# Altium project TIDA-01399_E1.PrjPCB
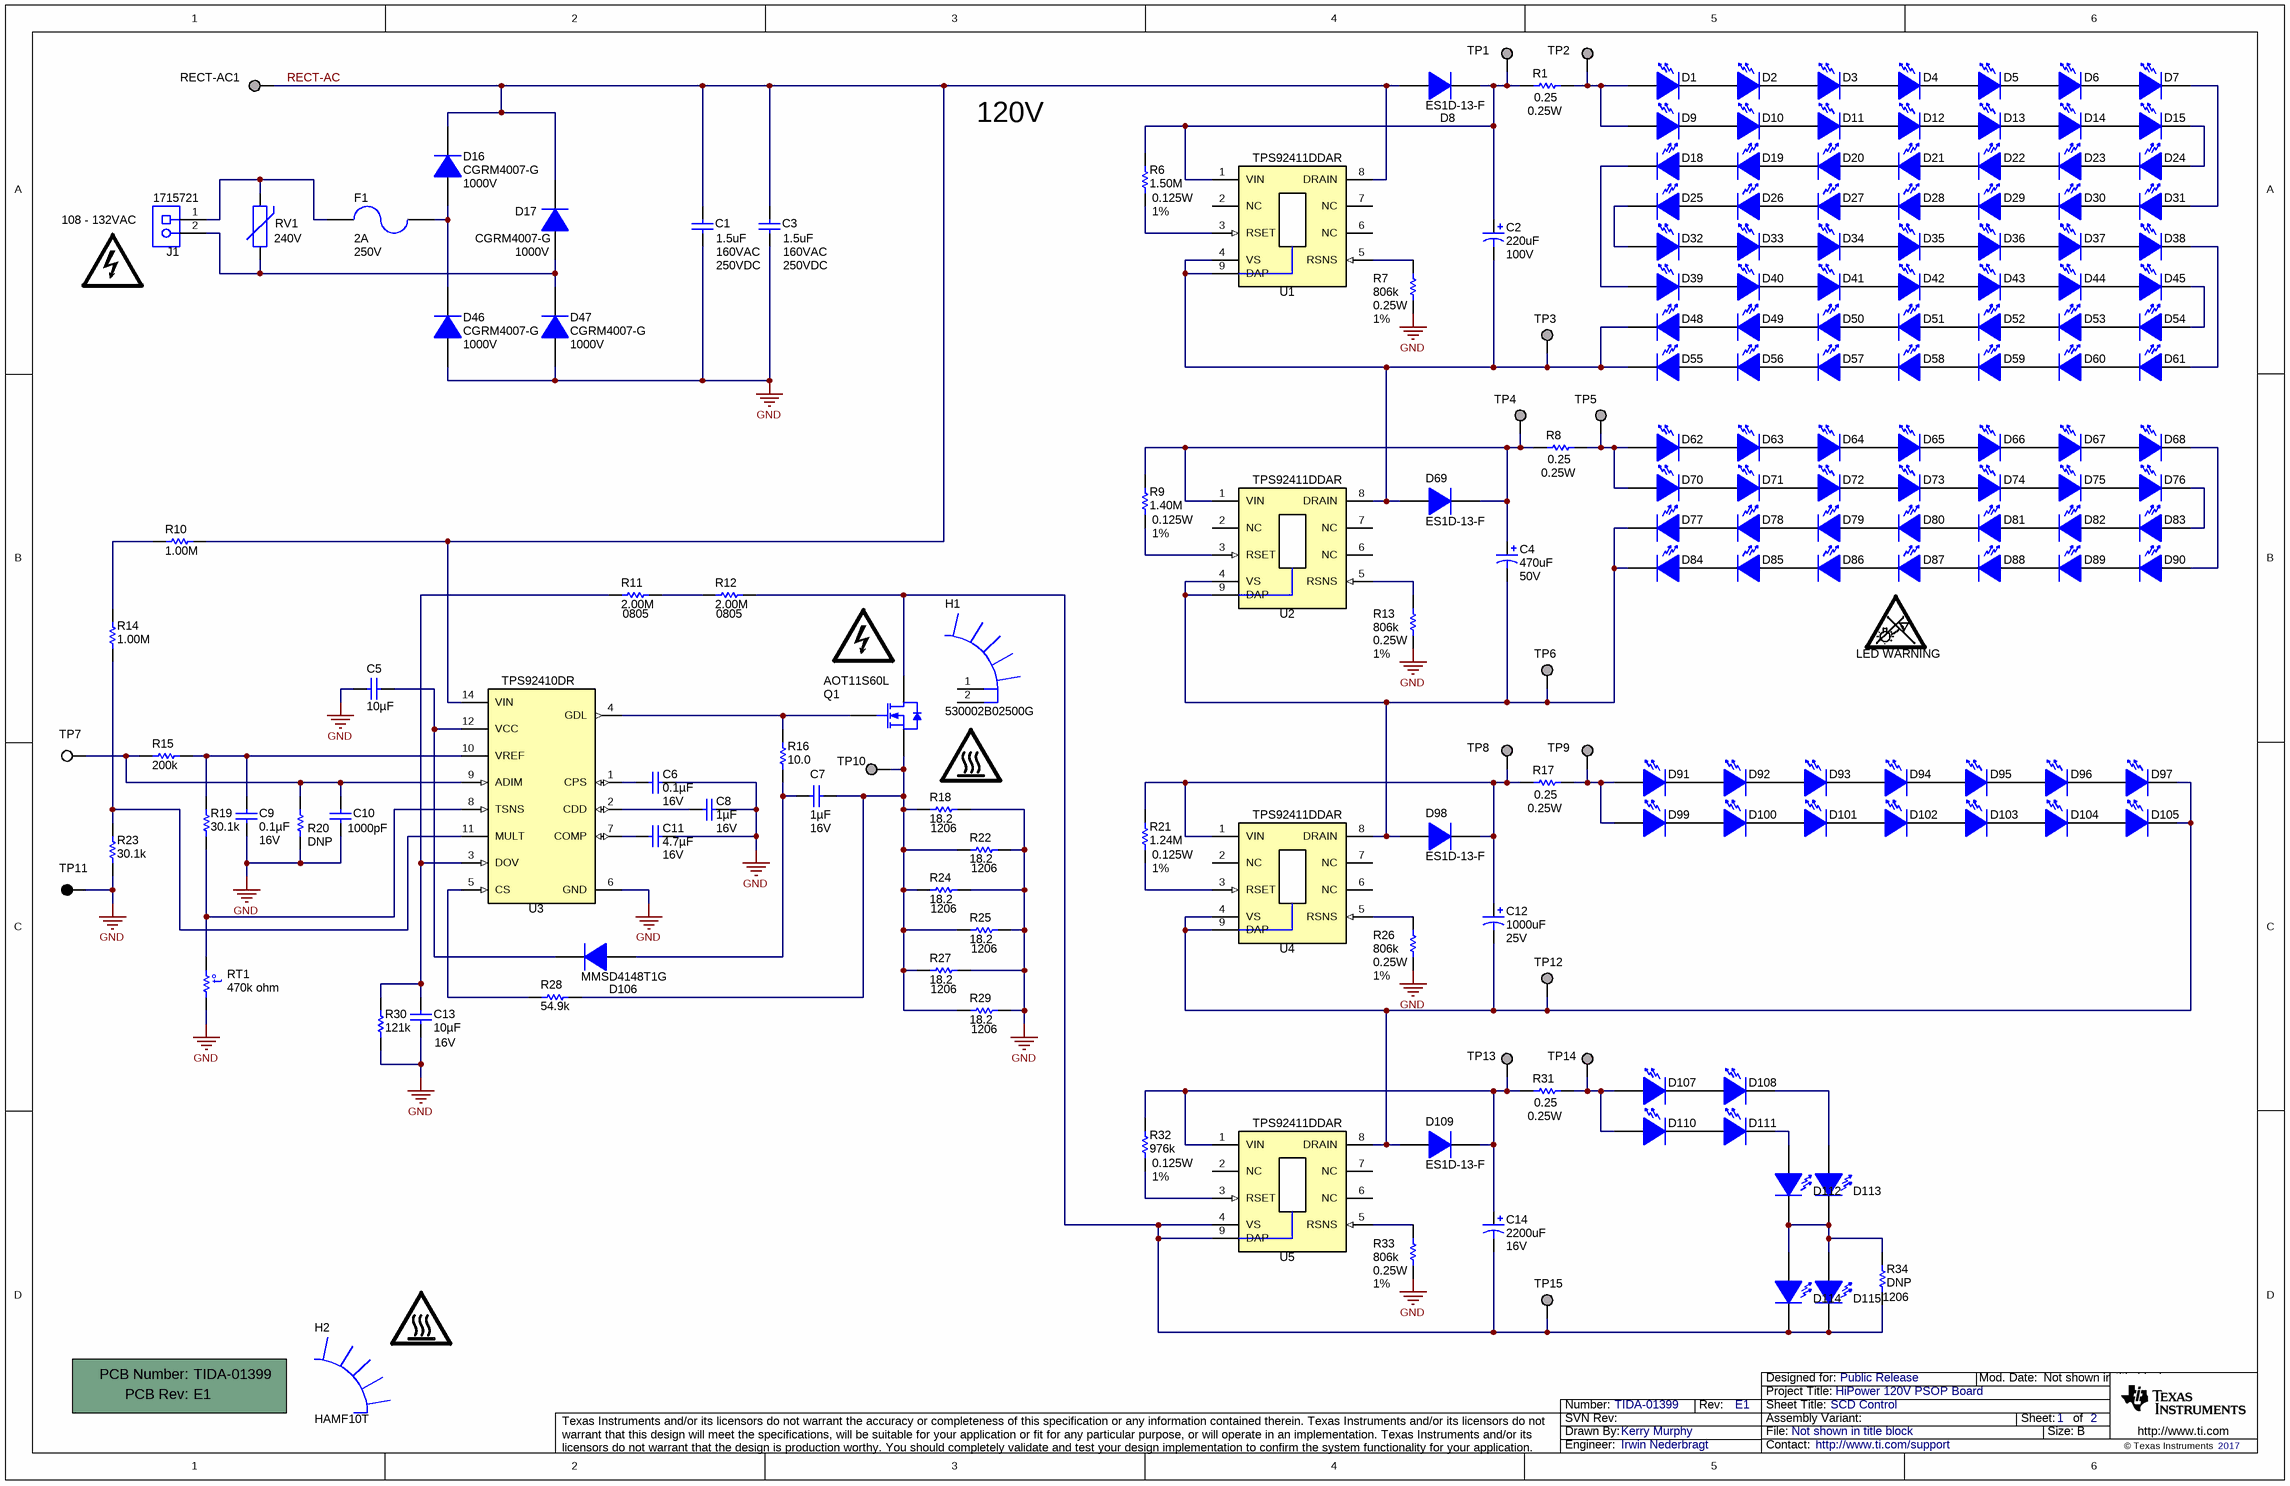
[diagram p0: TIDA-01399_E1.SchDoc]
CopyrightYear: 2017; PCB_Layout: Kerry Murphy; PCB_Rev: E1; PRJ_Customer: Public Release; PRJ_Engineer: Irwin Nederbragt; PRJ_Number: TIDA-01399; PRJ_Title: HiPower 120V PSOP Board; SCH_Rev: E1; TechSupport: http://www.ti.com/support
1 sheet, 193 parts. Net scope: global (net labels, ports and power ports of the same name join across sheets).
Board file: TIDA-01399_E1.PcbDoc

## Sheet TIDA-01399_E1.SchDoc: SCD Control
size 431 x 279 mm; Date: Not shown in title block; ApprovedBy: Not shown in title block; CheckedBy: Not shown in title block; Author: Not shown in title block; CompanyName: Not shown in title block; DrawnBy: Kerry Murphy; Engineer: Not shown in title block; Organization: Not shown in title block; Address1: Not shown in title block; Address2: Not shown in title block; Address3: Not shown in title block; Address4: Not shown in title block; DocumentNumber: 1; Revision: Use project parameter SCH_Rev; SheetNumber: 1; SheetTotal: 2; PageSetup: Record=PageOptions¦CenterHorizontal=True¦CenterVertical=True¦PrintScale=1.00¦XCorrection=1.00¦YCorrection=1.00¦PrintKind=0¦BorderSize=5000000¦LeftOffset=0¦BottomOffset=0¦Orientation=2¦PaperLength=1000¦PaperWidth=1000¦Scale=100¦PaperSource=15¦PrintQuality=600¦MediaType=1¦DitherType=10¦PaperKind=Letter¦PrintScaleMode=1

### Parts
!PCB1  Printed Circuit Board  (value not drawn)  (mechanical)
C1  value 1.5uF  VoltsAC: 160VAC  VoltsDC: 250VDC  [B32522C3155K]  (hidden comment: B32522C3155K)
C2  value 220uF  Value2Displayed: 100V  [UPW2A221MHD]  (hidden comment: UPW2A221MHD)
C3  value 1.5uF  VoltsAC: 160VAC  VoltsDC: 250VDC  [B32522C3155K]  (hidden comment: B32522C3155K)
C4  value 470uF  Value2Displayed: 50V  [UPW1H471MHD]  (hidden comment: UPW2A221MHD)
C5  ValueDisplayed: 10µF  [1206_190]  (hidden comment: C3216X7R1E106M160AE)
C6  ValueDisplayed: 0.1µF  Value2: 16V  [0603_HV]  (hidden comment: GRM188R71C104KA01D)
C7  ValueDisplayed: 1µF  Value2: 16V  [0603_HV]  (hidden comment: GRM188R71C105KA12D)
C8  ValueDisplayed: 1µF  Value2: 16V  [0603_HV]  (hidden comment: GRM188R71C105KA12D)
C9  ValueDisplayed: 0.1µF  Value2: 16V  [0603_HV]  (hidden comment: GRM188R71C104KA01D)
C10  ValueDisplayed: 1000pF  [0603_HV]  (hidden comment: GRM188R71H102KA01D)
C11  ValueDisplayed: 4.7µF  Value2: 16V  [0805_HV]  (hidden comment: GRM21BR71C475KA73L)
C12  value 1000uF  Value2Displayed: 25V  [UPW1E102MHD]  (hidden comment: UPW1E102MHD)
C13  ValueDisplayed: 10µF  Value2: 16V  [0805_HV]  (hidden comment: 0805YD106KAT2A)
C14  value 2200uF  Value2Displayed: 16V  [UPW1C222MHD]  (hidden comment: UPW1C222MHD)
D1  SPMWHT328FD5WAU0S0  [SPMWHT328FD5WAU0S0]  (value not drawn)
D2  SPMWHT328FD5WAU0S0  [SPMWHT328FD5WAU0S0]  (value not drawn)
D3  SPMWHT328FD5WAU0S0  [SPMWHT328FD5WAU0S0]  (value not drawn)
D4  SPMWHT328FD5WAU0S0  [SPMWHT328FD5WAU0S0]  (value not drawn)
D5  SPMWHT328FD5WAU0S0  [SPMWHT328FD5WAU0S0]  (value not drawn)
D6  SPMWHT328FD5WAU0S0  [SPMWHT328FD5WAU0S0]  (value not drawn)
D7  SPMWHT328FD5WAU0S0  [SPMWHT328FD5WAU0S0]  (value not drawn)
D8  ES1D-13-F  [SMA]
D9  SPMWHT328FD5WAU0S0  [SPMWHT328FD5WAU0S0]  (value not drawn)
D10  SPMWHT328FD5WAU0S0  [SPMWHT328FD5WAU0S0]  (value not drawn)
D11  SPMWHT328FD5WAU0S0  [SPMWHT328FD5WAU0S0]  (value not drawn)
D12  SPMWHT328FD5WAU0S0  [SPMWHT328FD5WAU0S0]  (value not drawn)
D13  SPMWHT328FD5WAU0S0  [SPMWHT328FD5WAU0S0]  (value not drawn)
D14  SPMWHT328FD5WAU0S0  [SPMWHT328FD5WAU0S0]  (value not drawn)
D15  SPMWHT328FD5WAU0S0  [SPMWHT328FD5WAU0S0]  (value not drawn)
D16  CGRM4007-G  value 1000V  [MINI-SMA]
D17  CGRM4007-G  value 1000V  [MINI-SMA]
D18  SPMWHT328FD5WAU0S0  [SPMWHT328FD5WAU0S0]  (value not drawn)
D19  SPMWHT328FD5WAU0S0  [SPMWHT328FD5WAU0S0]  (value not drawn)
D20  SPMWHT328FD5WAU0S0  [SPMWHT328FD5WAU0S0]  (value not drawn)
D21  SPMWHT328FD5WAU0S0  [SPMWHT328FD5WAU0S0]  (value not drawn)
D22  SPMWHT328FD5WAU0S0  [SPMWHT328FD5WAU0S0]  (value not drawn)
D23  SPMWHT328FD5WAU0S0  [SPMWHT328FD5WAU0S0]  (value not drawn)
D24  SPMWHT328FD5WAU0S0  [SPMWHT328FD5WAU0S0]  (value not drawn)
D25  SPMWHT328FD5WAU0S0  [SPMWHT328FD5WAU0S0]  (value not drawn)
D26  SPMWHT328FD5WAU0S0  [SPMWHT328FD5WAU0S0]  (value not drawn)
D27  SPMWHT328FD5WAU0S0  [SPMWHT328FD5WAU0S0]  (value not drawn)
D28  SPMWHT328FD5WAU0S0  [SPMWHT328FD5WAU0S0]  (value not drawn)
D29  SPMWHT328FD5WAU0S0  [SPMWHT328FD5WAU0S0]  (value not drawn)
D30  SPMWHT328FD5WAU0S0  [SPMWHT328FD5WAU0S0]  (value not drawn)
D31  SPMWHT328FD5WAU0S0  [SPMWHT328FD5WAU0S0]  (value not drawn)
D32  SPMWHT328FD5WAU0S0  [SPMWHT328FD5WAU0S0]  (value not drawn)
D33  SPMWHT328FD5WAU0S0  [SPMWHT328FD5WAU0S0]  (value not drawn)
D34  SPMWHT328FD5WAU0S0  [SPMWHT328FD5WAU0S0]  (value not drawn)
D35  SPMWHT328FD5WAU0S0  [SPMWHT328FD5WAU0S0]  (value not drawn)
D36  SPMWHT328FD5WAU0S0  [SPMWHT328FD5WAU0S0]  (value not drawn)
D37  SPMWHT328FD5WAU0S0  [SPMWHT328FD5WAU0S0]  (value not drawn)
D38  SPMWHT328FD5WAU0S0  [SPMWHT328FD5WAU0S0]  (value not drawn)
D39  SPMWHT328FD5WAU0S0  [SPMWHT328FD5WAU0S0]  (value not drawn)
D40  SPMWHT328FD5WAU0S0  [SPMWHT328FD5WAU0S0]  (value not drawn)
D41  SPMWHT328FD5WAU0S0  [SPMWHT328FD5WAU0S0]  (value not drawn)
D42  SPMWHT328FD5WAU0S0  [SPMWHT328FD5WAU0S0]  (value not drawn)
D43  SPMWHT328FD5WAU0S0  [SPMWHT328FD5WAU0S0]  (value not drawn)
D44  SPMWHT328FD5WAU0S0  [SPMWHT328FD5WAU0S0]  (value not drawn)
D45  SPMWHT328FD5WAU0S0  [SPMWHT328FD5WAU0S0]  (value not drawn)
D46  CGRM4007-G  value 1000V  [MINI-SMA]
D47  CGRM4007-G  value 1000V  [MINI-SMA]
D48  SPMWHT328FD5WAU0S0  [SPMWHT328FD5WAU0S0]  (value not drawn)
D49  SPMWHT328FD5WAU0S0  [SPMWHT328FD5WAU0S0]  (value not drawn)
D50  SPMWHT328FD5WAU0S0  [SPMWHT328FD5WAU0S0]  (value not drawn)
D51  SPMWHT328FD5WAU0S0  [SPMWHT328FD5WAU0S0]  (value not drawn)
D52  SPMWHT328FD5WAU0S0  [SPMWHT328FD5WAU0S0]  (value not drawn)
D53  SPMWHT328FD5WAU0S0  [SPMWHT328FD5WAU0S0]  (value not drawn)
D54  SPMWHT328FD5WAU0S0  [SPMWHT328FD5WAU0S0]  (value not drawn)
D55  SPMWHT328FD5WAU0S0  [SPMWHT328FD5WAU0S0]  (value not drawn)
D56  SPMWHT328FD5WAU0S0  [SPMWHT328FD5WAU0S0]  (value not drawn)
D57  SPMWHT328FD5WAU0S0  [SPMWHT328FD5WAU0S0]  (value not drawn)
D58  SPMWHT328FD5WAU0S0  [SPMWHT328FD5WAU0S0]  (value not drawn)
D59  SPMWHT328FD5WAU0S0  [SPMWHT328FD5WAU0S0]  (value not drawn)
D60  SPMWHT328FD5WAU0S0  [SPMWHT328FD5WAU0S0]  (value not drawn)
D61  SPMWHT328FD5WAU0S0  [SPMWHT328FD5WAU0S0]  (value not drawn)
D62  SPMWHT328FD5WAU0S0  [SPMWHT328FD5WAU0S0]  (value not drawn)
D63  SPMWHT328FD5WAU0S0  [SPMWHT328FD5WAU0S0]  (value not drawn)
D64  SPMWHT328FD5WAU0S0  [SPMWHT328FD5WAU0S0]  (value not drawn)
D65  SPMWHT328FD5WAU0S0  [SPMWHT328FD5WAU0S0]  (value not drawn)
D66  SPMWHT328FD5WAU0S0  [SPMWHT328FD5WAU0S0]  (value not drawn)
D67  SPMWHT328FD5WAU0S0  [SPMWHT328FD5WAU0S0]  (value not drawn)
D68  SPMWHT328FD5WAU0S0  [SPMWHT328FD5WAU0S0]  (value not drawn)
D69  ES1D-13-F  [SMA]
D70  SPMWHT328FD5WAU0S0  [SPMWHT328FD5WAU0S0]  (value not drawn)
D71  SPMWHT328FD5WAU0S0  [SPMWHT328FD5WAU0S0]  (value not drawn)
D72  SPMWHT328FD5WAU0S0  [SPMWHT328FD5WAU0S0]  (value not drawn)
D73  SPMWHT328FD5WAU0S0  [SPMWHT328FD5WAU0S0]  (value not drawn)
D74  SPMWHT328FD5WAU0S0  [SPMWHT328FD5WAU0S0]  (value not drawn)
D75  SPMWHT328FD5WAU0S0  [SPMWHT328FD5WAU0S0]  (value not drawn)
D76  SPMWHT328FD5WAU0S0  [SPMWHT328FD5WAU0S0]  (value not drawn)
D77  SPMWHT328FD5WAU0S0  [SPMWHT328FD5WAU0S0]  (value not drawn)
D78  SPMWHT328FD5WAU0S0  [SPMWHT328FD5WAU0S0]  (value not drawn)
D79  SPMWHT328FD5WAU0S0  [SPMWHT328FD5WAU0S0]  (value not drawn)
D80  SPMWHT328FD5WAU0S0  [SPMWHT328FD5WAU0S0]  (value not drawn)
D81  SPMWHT328FD5WAU0S0  [SPMWHT328FD5WAU0S0]  (value not drawn)
D82  SPMWHT328FD5WAU0S0  [SPMWHT328FD5WAU0S0]  (value not drawn)
D83  SPMWHT328FD5WAU0S0  [SPMWHT328FD5WAU0S0]  (value not drawn)
D84  SPMWHT328FD5WAU0S0  [SPMWHT328FD5WAU0S0]  (value not drawn)
D85  SPMWHT328FD5WAU0S0  [SPMWHT328FD5WAU0S0]  (value not drawn)
D86  SPMWHT328FD5WAU0S0  [SPMWHT328FD5WAU0S0]  (value not drawn)
D87  SPMWHT328FD5WAU0S0  [SPMWHT328FD5WAU0S0]  (value not drawn)
D88  SPMWHT328FD5WAU0S0  [SPMWHT328FD5WAU0S0]  (value not drawn)
D89  SPMWHT328FD5WAU0S0  [SPMWHT328FD5WAU0S0]  (value not drawn)
D90  SPMWHT328FD5WAU0S0  [SPMWHT328FD5WAU0S0]  (value not drawn)
D91  SPMWHT328FD5WAU0S0  [SPMWHT328FD5WAU0S0]  (value not drawn)
D92  SPMWHT328FD5WAU0S0  [SPMWHT328FD5WAU0S0]  (value not drawn)
D93  SPMWHT328FD5WAU0S0  [SPMWHT328FD5WAU0S0]  (value not drawn)
D94  SPMWHT328FD5WAU0S0  [SPMWHT328FD5WAU0S0]  (value not drawn)
D95  SPMWHT328FD5WAU0S0  [SPMWHT328FD5WAU0S0]  (value not drawn)
D96  SPMWHT328FD5WAU0S0  [SPMWHT328FD5WAU0S0]  (value not drawn)
D97  SPMWHT328FD5WAU0S0  [SPMWHT328FD5WAU0S0]  (value not drawn)
D98  ES1D-13-F  [SMA]
D99  SPMWHT328FD5WAU0S0  [SPMWHT328FD5WAU0S0]  (value not drawn)
D100  SPMWHT328FD5WAU0S0  [SPMWHT328FD5WAU0S0]  (value not drawn)
D101  SPMWHT328FD5WAU0S0  [SPMWHT328FD5WAU0S0]  (value not drawn)
D102  SPMWHT328FD5WAU0S0  [SPMWHT328FD5WAU0S0]  (value not drawn)
D103  SPMWHT328FD5WAU0S0  [SPMWHT328FD5WAU0S0]  (value not drawn)
D104  SPMWHT328FD5WAU0S0  [SPMWHT328FD5WAU0S0]  (value not drawn)
D105  SPMWHT328FD5WAU0S0  [SPMWHT328FD5WAU0S0]  (value not drawn)
D106  MMSD4148T1G  [SOD-123]
D107  SPMWHT328FD5WAU0S0  [SPMWHT328FD5WAU0S0]  (value not drawn)
D108  SPMWHT328FD5WAU0S0  [SPMWHT328FD5WAU0S0]  (value not drawn)
D109  ES1D-13-F  [SMA]
D110  SPMWHT328FD5WAU0S0  [SPMWHT328FD5WAU0S0]  (value not drawn)
D111  SPMWHT328FD5WAU0S0  [SPMWHT328FD5WAU0S0]  (value not drawn)
D112  SPMWHT328FD5WAU0S0  [SPMWHT328FD5WAU0S0]  (value not drawn)
D113  SPMWHT328FD5WAU0S0  [SPMWHT328FD5WAU0S0]  (value not drawn)
D114  SPMWHT328FD5WAU0S0  [SPMWHT328FD5WAU0S0]  (value not drawn)
D115  SPMWHT328FD5WAU0S0  [SPMWHT328FD5WAU0S0]  (value not drawn)
F1  VAC_V: 250V  Irating_A: 2A  [FUSE_RST]  (hidden comment: RST 2)
H1  530002B02500G  [Aavid_530002B02500G]
H2  HAMF10T  [Htsk_HAMF10T]
J1  1715721  [PhoenixContact_1715721]
LOGO2  DANGER HIGH VOLTAGE  [IEC_HighVoltage_Small]  (value not drawn)  (no BOM)
LOGO3  DANGER HIGH VOLTAGE  [IEC_HighVoltage_Small]  (value not drawn)  (no BOM)
LOGO4  CAUTION HOT SURFACE  [IEC_HotSurface_Small]  (value not drawn)  (no BOM)
LOGO5  CAUTION HOT SURFACE  [IEC_HotSurface_Small]  (value not drawn)  (no BOM)
LOGO6  LED WARNING  [LED_Warning]  (no BOM)
Q1  AOT11S60L  [TO-220AB]
R1  Power_W: 0.25W  ValueDisplayed: 0.25  [0805_HV]  (hidden comment: CSR0805FKR250)
R6  ValueDisplayed: 1.50M  Value1: 1%  Value2: 0.125W  [0805_HV]  (hidden comment: CRCW08051M50FKEA)
R7  ValueDisplayed: 806k  Value1: 1%  Value2: 0.25W  [1206]  (hidden comment: CRCW1206806KFKEA)
R8  Power_W: 0.25W  ValueDisplayed: 0.25  [0805_HV]  (hidden comment: CSR0805FKR250)
R9  ValueDisplayed: 1.40M  Value1: 1%  Value2: 0.125W  [0805_HV]  (hidden comment: CRCW08051M40FKEA)
R10  ValueDisplayed: 1.00M  [1206]  (hidden comment: CRCW12061M00FKEA)
R11  ValueDisplayed: 2.00M  PackageReference: 0805  [0805_HV]  (hidden comment: CRCW08052M00FKEA)
R12  ValueDisplayed: 2.00M  PackageReference: 0805  [0805_HV]  (hidden comment: CRCW08052M00FKEA)
R13  ValueDisplayed: 806k  Value1: 1%  Value2: 0.25W  [1206]  (hidden comment: CRCW1206806KFKEA)
R14  ValueDisplayed: 1.00M  [1206]  (hidden comment: CRCW12061M00FKEA)
R15  ValueDisplayed: 200k  [0603_HV]  (hidden comment: CRCW0603200KFKEA)
R16  ValueDisplayed: 10.0  [0603_HV]  (hidden comment: CRCW060310R0FKEA)
R17  Power_W: 0.25W  ValueDisplayed: 0.25  [0805_HV]  (hidden comment: CSR0805FKR250)
R18  ValueDisplayed: 18.2  [1206]  (hidden comment: CRCW120618R2FKEA)
R19  ValueDisplayed: 30.1k  [0603_HV]  (hidden comment: CRCW060330K1FKEA)
R20  DNP  [0603_HV]
R21  ValueDisplayed: 1.24M  Value1: 1%  Value2: 0.125W  [0805_HV]  (hidden comment: CRCW08051M24FKEA)
R22  ValueDisplayed: 18.2  [1206]  (hidden comment: CRCW120618R2FKEA)
R23  ValueDisplayed: 30.1k  [0603_HV]  (hidden comment: CRCW060330K1FKEA)
R24  ValueDisplayed: 18.2  [1206]  (hidden comment: CRCW120618R2FKEA)
R25  ValueDisplayed: 18.2  [1206]  (hidden comment: CRCW120618R2FKEA)
R26  ValueDisplayed: 806k  Value1: 1%  Value2: 0.25W  [1206]  (hidden comment: CRCW1206806KFKEA)
R27  ValueDisplayed: 18.2  [1206]  (hidden comment: CRCW120618R2FKEA)
R28  ValueDisplayed: 54.9k  [0603_HV]  (hidden comment: CRCW060354K9FKEA)
R29  ValueDisplayed: 18.2  [1206]  (hidden comment: CRCW120618R2FKEA)
R30  ValueDisplayed: 121k  [0603_HV]  (hidden comment: CRCW0603121KFKEA)
R31  Power_W: 0.25W  ValueDisplayed: 0.25  [0805_HV]  (hidden comment: CSR0805FKR250)
R32  ValueDisplayed: 976k  Value1: 1%  Value2: 0.125W  [0805_HV]  (hidden comment: CRCW0805976KFKEA)
R33  ValueDisplayed: 806k  Value1: 1%  Value2: 0.25W  [1206]  (hidden comment: CRCW1206806KFKEA)
R34  DNP  [1206]
RECT-AC1  Suggest using a net name here  [Keystone1502-2]  (value not drawn)
RT1  value 470k ohm  [0603_HV]  (hidden comment: NCP18WM474E03RB)
RV1  Varistor Voltage (Typ): 240V  [MOV-10D241K]  (hidden comment: MOV-10D241K)
TP1  Suggest using a net name here  [Keystone1502-2]  (value not drawn)
TP2  Suggest using a net name here  [Keystone1502-2]  (value not drawn)
TP3  Suggest using a net name here  [Keystone1502-2]  (value not drawn)
TP4  Suggest using a net name here  [Keystone1502-2]  (value not drawn)
TP5  Suggest using a net name here  [Keystone1502-2]  (value not drawn)
TP6  Suggest using a net name here  [Keystone1502-2]  (value not drawn)
TP7  5002  [Keystone5002]  (value not drawn)
TP8  Suggest using a net name here  [Keystone1502-2]  (value not drawn)
TP9  Suggest using a net name here  [Keystone1502-2]  (value not drawn)
TP10  Suggest using a net name here  [Keystone1502-2]  (value not drawn)
TP11  5001  [Keystone5001]  (value not drawn)
TP12  Suggest using a net name here  [Keystone1502-2]  (value not drawn)
TP13  Suggest using a net name here  [Keystone1502-2]  (value not drawn)
TP14  Suggest using a net name here  [Keystone1502-2]  (value not drawn)
TP15  Suggest using a net name here  [Keystone1502-2]  (value not drawn)
U1  TPS92411DDAR  [DDA0008E_N]
U2  TPS92411DDAR  [DDA0008E_N]
U3  TPS92410DR  [D0013A_N]
U4  TPS92411DDAR  [DDA0008E_N]
U5  TPS92411DDAR  [DDA0008E_N]

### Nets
GND: C1.2 C3.2 C5.2 C6.1 C8.1 C9.2 C10.2 C11.1 C13.2 D46.2(A) D47.2(A) R7.1 R13.1 R18.2 R20.1 R22.2 R23.1 R24.2 R25.2 R26.1 R27.2 R29.2 R30.1 R33.1 RT1.1 TP11.1 U3.6(GND)
RECT-AC: C1.1 C3.1 D8.2(A) D16.1(K) D17.1(K) R10.1 RECT-AC1.1 U1.8(DRAIN) U3.14(VIN)
NetC2_1: C2.1(+) D8.1(K) R1.1 R6.2 TP1.1 U1.1(VIN)
NetC2_2: C2.2(-) D48.2(K) D55.2(K) D69.2(A) TP3.1 U1.4(VS) U1.9(DAP) U2.8(DRAIN)
NetC4_1: C4.1(+) D69.1(K) R8.1 R9.2 TP4.1 U2.1(VIN)
NetC4_2: C4.2(-) D77.2(K) D84.2(K) D98.2(A) TP6.1 U2.4(VS) U2.9(DAP) U4.8(DRAIN)
NetC5_1: C5.1 D106.1(K) U3.12(VCC)
NetC6_2: C6.2 U3.1(CPS)
NetC7_1: C7.1 Q1.3(S) R18.1 R22.1 R24.1 R25.1 R27.1 R28.2 R29.1 TP10.1
NetC7_2: C7.2 D106.2(A) R16.1
NetC8_2: C8.2 U3.2(CDD)
NetC9_1: C9.1 R15.2 R19.2 U3.10(VREF)
NetC10_1: C10.1 R15.1 R20.2 TP7.1 U3.9(ADIM)
NetC11_2: C11.2 U3.7(COMP)
NetC12_1: C12.1(+) D98.1(K) R17.1 R21.2 TP8.1 U4.1(VIN)
NetC12_2: C12.2(-) D97.2(K) D105.2(K) D109.2(A) TP12.1 U4.4(VS) U4.9(DAP) U5.8(DRAIN)
NetC13_1: C13.1 R11.1 R30.2 U3.3(DOV)
NetC14_1: C14.1(+) D109.1(K) R31.1 R32.2 TP13.1 U5.1(VIN)
NetC14_2: C14.2(-) D114.2(K) D115.2(K) Q1.2(D) R12.2 R34.1 TP15.1 U5.4(VS) U5.9(DAP)
NetD1_1: D1.1(A) D9.1(A) R1.2 TP2.1
NetD1_2: D1.2(K) D2.1(A)
NetD2_2: D2.2(K) D3.1(A)
NetD3_2: D3.2(K) D4.1(A)
NetD4_2: D4.2(K) D5.1(A)
NetD5_2: D5.2(K) D6.1(A)
NetD6_2: D6.2(K) D7.1(A)
NetD7_2: D7.2(K) D31.1(A)
NetD9_2: D9.2(K) D10.1(A)
NetD10_2: D10.2(K) D11.1(A)
NetD11_2: D11.2(K) D12.1(A)
NetD12_2: D12.2(K) D13.1(A)
NetD13_2: D13.2(K) D14.1(A)
NetD14_2: D14.2(K) D15.1(A)
NetD15_2: D15.2(K) D24.1(A)
NetD16_2: D16.2(A) D46.1(K) F1.1
NetD17_2: D17.2(A) D47.1(K) J1.2 RV1.1
NetD18_1: D18.1(A) D19.2(K)
NetD18_2: D18.2(K) D39.1(A)
NetD19_1: D19.1(A) D20.2(K)
NetD20_1: D20.1(A) D21.2(K)
NetD21_1: D21.1(A) D22.2(K)
NetD22_1: D22.1(A) D23.2(K)
NetD23_1: D23.1(A) D24.2(K)
NetD25_1: D25.1(A) D26.2(K)
NetD25_2: D25.2(K) D32.1(A)
NetD26_1: D26.1(A) D27.2(K)
NetD27_1: D27.1(A) D28.2(K)
NetD28_1: D28.1(A) D29.2(K)
NetD29_1: D29.1(A) D30.2(K)
NetD30_1: D30.1(A) D31.2(K)
NetD32_2: D32.2(K) D33.1(A)
NetD33_2: D33.2(K) D34.1(A)
NetD34_2: D34.2(K) D35.1(A)
NetD35_2: D35.2(K) D36.1(A)
NetD36_2: D36.2(K) D37.1(A)
NetD37_2: D37.2(K) D38.1(A)
NetD38_2: D38.2(K) D61.1(A)
NetD39_2: D39.2(K) D40.1(A)
NetD40_2: D40.2(K) D41.1(A)
NetD41_2: D41.2(K) D42.1(A)
NetD42_2: D42.2(K) D43.1(A)
NetD43_2: D43.2(K) D44.1(A)
NetD44_2: D44.2(K) D45.1(A)
NetD45_2: D45.2(K) D54.1(A)
NetD48_1: D48.1(A) D49.2(K)
NetD49_1: D49.1(A) D50.2(K)
NetD50_1: D50.1(A) D51.2(K)
NetD51_1: D51.1(A) D52.2(K)
NetD52_1: D52.1(A) D53.2(K)
NetD53_1: D53.1(A) D54.2(K)
NetD55_1: D55.1(A) D56.2(K)
NetD56_1: D56.1(A) D57.2(K)
NetD57_1: D57.1(A) D58.2(K)
NetD58_1: D58.1(A) D59.2(K)
NetD59_1: D59.1(A) D60.2(K)
NetD60_1: D60.1(A) D61.2(K)
NetD62_1: D62.1(A) D70.1(A) R8.2 TP5.1
NetD62_2: D62.2(K) D63.1(A)
NetD63_2: D63.2(K) D64.1(A)
NetD64_2: D64.2(K) D65.1(A)
NetD65_2: D65.2(K) D66.1(A)
NetD66_2: D66.2(K) D67.1(A)
NetD67_2: D67.2(K) D68.1(A)
NetD68_2: D68.2(K) D90.1(A)
NetD70_2: D70.2(K) D71.1(A)
NetD71_2: D71.2(K) D72.1(A)
NetD72_2: D72.2(K) D73.1(A)
NetD73_2: D73.2(K) D74.1(A)
NetD74_2: D74.2(K) D75.1(A)
NetD75_2: D75.2(K) D76.1(A)
NetD76_2: D76.2(K) D83.1(A)
NetD77_1: D77.1(A) D78.2(K)
NetD78_1: D78.1(A) D79.2(K)
NetD79_1: D79.1(A) D80.2(K)
NetD80_1: D80.1(A) D81.2(K)
NetD81_1: D81.1(A) D82.2(K)
NetD82_1: D82.1(A) D83.2(K)
NetD84_1: D84.1(A) D85.2(K)
NetD85_1: D85.1(A) D86.2(K)
NetD86_1: D86.1(A) D87.2(K)
NetD87_1: D87.1(A) D88.2(K)
NetD88_1: D88.1(A) D89.2(K)
NetD89_1: D89.1(A) D90.2(K)
NetD91_1: D91.1(A) D99.1(A) R17.2 TP9.1
NetD91_2: D91.2(K) D92.1(A)
NetD92_2: D92.2(K) D93.1(A)
NetD93_2: D93.2(K) D94.1(A)
NetD94_2: D94.2(K) D95.1(A)
NetD95_2: D95.2(K) D96.1(A)
NetD96_2: D96.2(K) D97.1(A)
NetD99_2: D99.2(K) D100.1(A)
NetD100_2: D100.2(K) D101.1(A)
NetD101_2: D101.2(K) D102.1(A)
NetD102_2: D102.2(K) D103.1(A)
NetD103_2: D103.2(K) D104.1(A)
NetD104_2: D104.2(K) D105.1(A)
NetD107_1: D107.1(A) D110.1(A) R31.2 TP14.1
NetD107_2: D107.2(K) D108.1(A)
NetD108_2: D108.2(K) D113.1(A)
NetD110_2: D110.2(K) D111.1(A)
NetD111_2: D111.2(K) D112.1(A)
NetD112_2: D112.2(K) D113.2(K) D114.1(A) D115.1(A) R34.2
NetF1_2: F1.2 J1.1 RV1.2
NetQ1_1: Q1.1(G) R16.2 U3.4(GDL)
NetR6_1: R6.1 U1.3(RSET)
NetR7_2: R7.2 U1.5(RSNS)
NetR9_1: R9.1 U2.3(RSET)
NetR10_2: R10.2 R14.2
NetR11_2: R11.2 R12.1
NetR13_2: R13.2 U2.5(RSNS)
NetR14_1: R14.1 R23.2 U3.11(MULT)
NetR19_1: R19.1 RT1.2 U3.8(TSNS)
NetR21_1: R21.1 U4.3(RSET)
NetR26_2: R26.2 U4.5(RSNS)
NetR28_1: R28.1 U3.5(CS)
NetR32_1: R32.1 U5.3(RSET)
NetR33_2: R33.2 U5.5(RSNS)

Not connected (* = marked no-connect by the designer): H1 1 2; U1 2(NC) 6(NC) 7(NC); U2 2(NC) 6(NC) 7(NC); U4 2(NC) 6(NC) 7(NC); U5 2(NC) 6(NC) 7(NC)

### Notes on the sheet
- 120V
- 108 - 132VAC

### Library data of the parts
!PCB1 = PCB: Manufacturer: Any; PartNumber: TIDA-01399; SymbolCreator: a0412235
C1 C3 = Capacitor: CAP, Film, 1.5uF, 160VAC, 250VDC, 10%, Radial; Manufacturer: EPCOS; Polarized: N; U/M: EA; lead_free_status: Lead Free; lead_length: 0.006; dielectric_material: Polyester; voltage_rating_dc: 250.0; size_height: 0.0175; size_length: 0.018
C2 = UPW2A221MHD: CAP, AL, 220µF, 100V, +/- 20%, Radial; Manufacturer: Nichicon; Tolerance_%: 20; VDC_V: 100
C4 = UPW2A221MHD: CAP, AL, 470µF, 50V, +/- 20%, Radial; Manufacturer: Nichicon; Tolerance_%: 20; VDC_V: 50
C5 = C3216X7R1E106M160AE: CAP, CERM, 10 µF, 25 V, +/- 20%, X7R, 1206_190; Manufacturer: TDK; Polarized: N; CompType: Capacitor; Value: 10uF; U/M: EA; Cap_F: 0.00001; Tolerance_%: 20; Value1: Unknown; VDC_V: 25; Value2: 25V; TaMin_C: -55; TaMax_C: 125; Cap_Case: 1206; SizeArea_mm2: 5.12; SizeAreaWB_mm2: 10.92; SizeX_mm: 3.2; SizeY_mm: 1.6; SizeZ_mm: 1.9; AEC Category: Q200
C6 C9 = GRM188R71C104KA01D: CAP, CERM, 0.1 µF, 16 V, +/- 10%, X7R, 0603; Manufacturer: MuRata; Polarized: N; CompType: Capacitor; Value: 0.1uF; U/M: EA; Cap_F: 0.0000001; Tolerance_%: 10; Value1: Unknown; VDC_V: 16; TaMin_C: -55; TaMax_C: 125; Cap_Case: 0603; SizeArea_mm2: 1.28; SizeAreaWB_mm2: 4.68; SizeX_mm: 1.6; SizeY_mm: 0.8; SizeZ_mm: 1; AEC Category: Q200
C7 C8 = GRM188R71C105KA12D: CAP, CERM, 1 µF, 16 V, +/- 10%, X7R, 0603; Manufacturer: MuRata; Polarized: N; CompType: Capacitor; Value: 1uF; U/M: EA; Cap_F: 0.000001; Tolerance_%: 10; ESR_ohm: 0.011; Value1: 0.011 ohm; VDC_V: 16; TaMin_C: -55; TaMax_C: 125; Cap_Case: 0603; SizeArea_mm2: 1.28; SizeAreaWB_mm2: 4.68; SizeX_mm: 1.6; SizeY_mm: 0.8; SizeZ_mm: 1; AEC Category: Q200
C10 = GRM188R71H102KA01D: CAP, CERM, 1000 pF, 50 V, +/- 10%, X7R, 0603; Manufacturer: MuRata; Polarized: N; CompType: Capacitor; Value: 1000pF; U/M: EA; Cap_F: 0.000000001; Tolerance_%: 10; Value1: Unknown; VDC_V: 50; Value2: 50V; TaMin_C: -55; TaMax_C: 125; Cap_Case: 0603; SizeArea_mm2: 1.28; SizeAreaWB_mm2: 4.68; SizeX_mm: 1.6; SizeY_mm: 0.8; SizeZ_mm: 1; AEC Category: Q200
C11 = GRM21BR71C475KA73L: CAP, CERM, 4.7 µF, 16 V, +/- 10%, X7R, 0805; Manufacturer: MuRata; Polarized: N; CompType: Capacitor; Value: 4.7uF; U/M: EA; Cap_F: 0.0000047; Tolerance_%: 10; ESR_ohm: 0.006; Value1: 0.006 ohm; VDC_V: 16; TaMin_C: -55; TaMax_C: 125; Cap_Case: 0805; SizeArea_mm2: 2.5; SizeAreaWB_mm2: 6.75; SizeX_mm: 2; SizeY_mm: 1.25; SizeZ_mm: 1.45; AEC Category: Q200
C12 = UPW1E102MHD: CAP, AL, 1000µF, 25V, +/- 20%, Radial; Manufacturer: Nichicon; U/M: EA; Tolerance_%: 20; VDC_V: 25
C13 = 0805YD106KAT2A: CAP, CERM, 10 µF, 16 V, +/- 10%, X5R, 0805; Manufacturer: AVX; Polarized: N; CompType: Capacitor; Value: 10uF; U/M: EA; Cap_F: 0.00001; Tolerance_%: 10; Value1: Unknown; VDC_V: 16; TaMin_C: -55; TaMax_C: 85; Cap_Case: 0805; SizeArea_mm2: 2.5; SizeAreaWB_mm2: 6.75; SizeX_mm: 2; SizeY_mm: 1.25; SizeZ_mm: 1.45; AEC Category: Q200
C14 = UPW1C222MHD: CAP, AL, 2200µF, 16V, +/- 20%, Radial; Manufacturer: Nichicon; Tolerance_%: 20; VDC_V: 16
D1-D7 D9-D15 D18-D45 D48-D68 D70-D97 D99-D105 D107 D108 D110-D115 = LED: LED, White, 3500K, 80 CRI, SMD; Manufacturer: Samsung Semiconductor, Inc.; U/M: EA; Color: White, Warm; Flux @ 85°C, Current - Test: 62 lm (58 lm ~ 66 lm); Current - Test: 150mA; Voltage - Forward (Vf) (Typ): 2.85V; Lumens/Watt @ Current - Test: 145 lm/W; CRI (Color Rendering Index): 80; Current - Max: 500mA; Angle: 115°; Thermal Resistance of Package: 7°C/W
D8 D69 D98 D109 = ES1D-13-F: Diode, Ultrafast, 200 V, 1 A, SMA; Manufacturer: Diodes Inc.; U/M: EA; Vf_V: 0.92; Value: 200V; Value1: 1A; Value2: 0.92V; Io_A: 1; Vr_V: 200; TJmax_C: 150; RJC_CperW: 25; SizeAreaWB_mm2: 37.3428; SizeArea_mm2: 16.3228; SizeX_mm: 5.59; SizeY_mm: 2.92; SizeZ_mm: 2.87; AEC Category: Q101
D16 D17 D46 D47 = CGRM4007-G: Diode, P-N, 1000V, 1A, 3.9x1.7x1.8mm; Manufacturer: Comchip Technology; U/M: EA; Vf_V: 1.1; Value2: 1.1V; Io_A: 1; Vr_V: 1000; TJmax_C: 150
D106 = MMSD4148T1G: Diode, Switching, 100 V, 0.2 A, SOD-123; Manufacturer: ON Semiconductor; U/M: EA; Vf_V: 1; Value: 100V; Value1: 0.2A; Value2: 1V; Io_A: 0.2; Vr_V: 100; TJmax_C: 150; SizeAreaWB_mm2: 13.095; SizeArea_mm2: 6.545; SizeX_mm: 3.85; SizeY_mm: 1.7; SizeZ_mm: 1.35; AEC Category: Q101
F1 = RST 1: Fuse, 2 A, 250VAC/VDC, TH; Manufacturer: Bel Fuse; VDC_V: 250; Rtyp_Ohm: 0.07; MeltingTyp: 7
H1 = 530002B02500G: Heat Sink, TO-220, Vertical; Manufacturer: Aavid; SymbolCreator: a0799628
H2 = Htsk_HAMF10T: HEATSINK PFE1000F; Manufacturer: TDK-Lambda Americas Inc
J1 = 1715721: Terminal Block, 5.08 mm, 2x1, TH; Manufacturer: Phoenix Contact; SymbolCreator: a0412235; Pitch_mm: 5.08; Gender: Female; Row_Count: 1; ContactFinish: Tin; Current_A: 17.5; Voltage_V: 400; Cert_CSA: Y; Cert_CULUS: N
LOGO2 LOGO3 = IEC_HighVoltage: IEC 61010-1 High Voltage Warning; SymbolCreator: a0412235
LOGO4 LOGO5 = IEC_HotSurface: IEC 61010-1 Hot Surface Warning; SymbolCreator: a0412235
LOGO6 = LED_Warning: LED Warning Symbol; SymbolCreator: a0412235
Q1 = MOSFET_N_D2G1S3: MOSFET, N-CH, xxV, xxxA, [PackageReference]; Manufacturer: Alpha & Omega Semiconductor Inc.; U/M: EA; Power - Max: 178W; Gate Charge (Qg) @ Vgs: 11nC @ 10V; Input Capacitance (Ciss) @ Vds: 545pF @ 100V; Vgs(th) (Max) @ Id: 4.1V @ 250µA; Current - Continuous Drain (Id) @ 25°C: 11A (Tc); VdsMax_V: 600V; FET Type: MOSFET N-Channel, Metal Oxide; Rds On (Max) @ Id, Vgs: 399 mOhm @ 3.8A, 10V; FET Feature: Standard
R1 R8 R17 R31 = Resistor: RES, 0.25 ohm, 1%, 0.25W, 0805; Manufacturer: Stackpole Electronics Inc.; Value: 0.25; U/M: EA; TempCo: ±200ppm/°C
R6 = CRCW08051M50FKEA: RES, 1.50 M, 1%, 0.125 W, 0805; Manufacturer: Vishay-Dale; CompType: Resistor; Value: 1.50Meg; Res_ohm: 1500000; Value_Code: 1M50; Tolerance_%: 1; Power_W: 0.125; VDC_V: 150; TempCo: 100 ppm/C; SizeArea_mm2: 2.5; SizeX_mm: 2; SizeY_mm: 1.25; SizeZ_mm: 1.45; EIA_Code: E96; U/M: EA; AEC Category: Q200
R7 R13 R26 R33 = CRCW1206806KFKEA: RES, 806 k, 1%, 0.25 W, 1206; Manufacturer: Vishay-Dale; CompType: Resistor; Value: 806k; Res_ohm: 806000; Tolerance_%: 1; Power_W: 0.25; VDC_V: 200; TempCo: 100 ppm/C; SizeArea_mm2: 5.12; SizeX_mm: 3.2; SizeY_mm: 1.6; SizeZ_mm: 1.35; EIA_Code: E96; U/M: EA; AEC Category: Q200
R9 = CRCW08051M40FKEA: RES, 1.40 M, 1%, 0.125 W, 0805; Manufacturer: Vishay-Dale; CompType: Resistor; Value: 1.40Meg; Res_ohm: 1400000; Value_Code: 1M40; Tolerance_%: 1; Power_W: 0.125; VDC_V: 150; TempCo: 100 ppm/C; SizeArea_mm2: 2.5; SizeX_mm: 2; SizeY_mm: 1.25; SizeZ_mm: 1.45; EIA_Code: E96; U/M: EA; AEC Category: Q200
R10 R14 = CRCW12061M00FKEA: RES, 1.00 M, 1%, 0.25 W, 1206; Manufacturer: Vishay-Dale; CompType: Resistor; Value: 1.00Meg; Res_ohm: 1000000; Value_Code: 1M00; Tolerance_%: 1; Power_W: 0.25; Value2: 0.25W; VDC_V: 200; TempCo: 100 ppm/C; SizeArea_mm2: 5.12; SizeX_mm: 3.2; SizeY_mm: 1.6; SizeZ_mm: 1.35; EIA_Code: E96; U/M: EA; AEC Category: Q200
R11 R12 = CRCW08052M00FKEA: RES, 2.00 M, 1%, 0.125 W, 0805; Manufacturer: Vishay-Dale; CompType: Resistor; Value: 2.00Meg; Res_ohm: 2000000; Value_Code: 2M00; Tolerance_%: 1; Power_W: 0.125; Value2: 0.125W; VDC_V: 150; TempCo: 100 ppm/C; SizeArea_mm2: 2.5; SizeX_mm: 2; SizeY_mm: 1.25; SizeZ_mm: 1.45; EIA_Code: E96; U/M: EA; AEC Category: Q200
R15 = CRCW0603200KFKEA: RES, 200 k, 1%, 0.1 W, 0603; Manufacturer: Vishay-Dale; CompType: Resistor; Value: 200k; Res_ohm: 200000; Tolerance_%: 1; Power_W: 0.1; Value2: 0.1W; VDC_V: 75; TempCo: 100 ppm/C; SizeArea_mm2: 1.28; SizeX_mm: 1.6; SizeY_mm: 0.8; EIA_Code: E96; U/M: EA; AEC Category: Q200
R16 = CRCW060310R0FKEA: RES, 10.0, 1%, 0.1 W, 0603; Manufacturer: Vishay-Dale; CompType: Resistor; Value: 10.0; Res_ohm: 10; Value_Code: 10R0; Tolerance_%: 1; Power_W: 0.1; Value2: 0.1W; VDC_V: 75; TempCo: 100 ppm/C; SizeArea_mm2: 1.28; SizeX_mm: 1.6; SizeY_mm: 0.8; EIA_Code: E96; U/M: EA; AEC Category: Q200
R18 R22 R24 R25 R27 R29 = CRCW120618R2FKEA: RES, 18.2, 1%, 0.25 W, 1206; Manufacturer: Vishay-Dale; CompType: Resistor; Value: 18.2; Value_Code: 18R2; Tolerance_%: 1; Power_W: 0.25; Value2: 0.25W; VDC_V: 200; TempCo: 100 ppm/C; SizeArea_mm2: 5.12; SizeX_mm: 3.2; SizeY_mm: 1.6; SizeZ_mm: 1.35; EIA_Code: E96; U/M: EA; AEC Category: Q200
R19 R23 = CRCW060330K1FKEA: RES, 30.1 k, 1%, 0.1 W, 0603; Manufacturer: Vishay-Dale; CompType: Resistor; Value: 30.1k; Res_ohm: 30100; Value_Code: 30k1; Tolerance_%: 1; Power_W: 0.1; Value2: 0.1W; VDC_V: 75; TempCo: 100 ppm/C; SizeArea_mm2: 1.28; SizeX_mm: 1.6; SizeY_mm: 0.8; EIA_Code: E96; U/M: EA; AEC Category: Q200
R20 = Resistor: Manufacturer: Used in BOM report; U/M: EA
R21 = CRCW08051M24FKEA: RES, 1.24 M, 1%, 0.125 W, 0805; Manufacturer: Vishay-Dale; CompType: Resistor; Value: 1.24Meg; Res_ohm: 1240000; Value_Code: 1M24; Tolerance_%: 1; Power_W: 0.125; VDC_V: 150; TempCo: 100 ppm/C; SizeArea_mm2: 2.5; SizeX_mm: 2; SizeY_mm: 1.25; SizeZ_mm: 1.45; EIA_Code: E96; U/M: EA; AEC Category: Q200
R28 = CRCW060354K9FKEA: RES, 54.9 k, 1%, 0.1 W, 0603; Manufacturer: Vishay-Dale; CompType: Resistor; Value: 54.9k; Res_ohm: 54900; Value_Code: 54k9; Tolerance_%: 1; Power_W: 0.1; Value2: 0.1W; VDC_V: 75; TempCo: 100 ppm/C; SizeArea_mm2: 1.28; SizeX_mm: 1.6; SizeY_mm: 0.8; EIA_Code: E96; U/M: EA; AEC Category: Q200
R30 = CRCW0603121KFKEA: RES, 121 k, 1%, 0.1 W, 0603; Manufacturer: Vishay-Dale; CompType: Resistor; Value: 121k; Res_ohm: 121000; Tolerance_%: 1; Power_W: 0.1; Value2: 0.1W; VDC_V: 75; TempCo: 100 ppm/C; SizeArea_mm2: 1.28; SizeX_mm: 1.6; SizeY_mm: 0.8; EIA_Code: E96; U/M: EA; AEC Category: Q200
R32 = CRCW0805976KFKEA: RES, 976 k, 1%, 0.125 W, 0805; Manufacturer: Vishay-Dale; CompType: Resistor; Value: 976k; Res_ohm: 976000; Tolerance_%: 1; Power_W: 0.125; VDC_V: 150; TempCo: 100 ppm/C; SizeArea_mm2: 2.5; SizeX_mm: 2; SizeY_mm: 1.25; SizeZ_mm: 1.45; EIA_Code: E96; U/M: EA; AEC Category: Q200
R34 = Resistor: U/M: EA
RECT-AC1 TP1-TP6 TP8-TP10 TP12-TP15 = 1502-2: Terminal, Turret, TH, Double; Manufacturer: Keystone; CompType: Turret Terminal
RT1 = NCP18WM474E03RB: Thermistor NTC, 470k ohm, 3%, 0603; Manufacturer: MuRata; Tolerance_%: 3; Power_W: 0.1; TaMin_C: -40; TaMax_C: 125; U/M: EA
RV1 = Varistor_MetalOxide: Varistor, 240VAC, 200VDC, 10mm, Radial; Manufacturer: Bourns Inc.; SymbolCreator: a0412235; CompType: MOV; U/M: EA; Number of Circuits: 1; Maximum AC Volts: 150VAC; Varistor Voltage (Min): 216V; Energy: 35J; Varistor Voltage (Max): 264V; Current - Surge: 2.5kA
TP7 = 5002: Test Point, Miniature, White, TH; Manufacturer: Keystone; CompType: Test Point Loop; ContactFinish: Silver
TP11 = 5001: Test Point, Miniature, Black, TH; Manufacturer: Keystone; CompType: Test Point Loop; ContactFinish: Silver
U1 U2 U4 U5 = TPS92411DDAR: Floating Switch for Offline AC Linear Direct Drive of LEDs with Low Ripple Current, DDA0008E (SOIC-8); Manufacturer: Texas Instruments; SymbolCreator: a0414679 / a0411947; SizeArea_mm2: 31; SizeAreaWB_mm2: 57.4; SizeX_mm: 5; SizeY_mm: 6.2; SizeZ_mm: 1.7; CompType: IC; U/M: EA
U3 = TPS92410DR: Switch Controlled Direct Drive Linear Controller for Offline LED Drivers, D0013A (SOIC-13); Manufacturer: Texas Instruments; SymbolCreator: x0208325; SizeArea_mm2: 51.9; SizeAreaWB_mm2: 85.2; SizeX_mm: 6; SizeY_mm: 8.65; SizeZ_mm: 1.75; CompType: IC; U/M: EA

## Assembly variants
001: not fitted R20 R34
